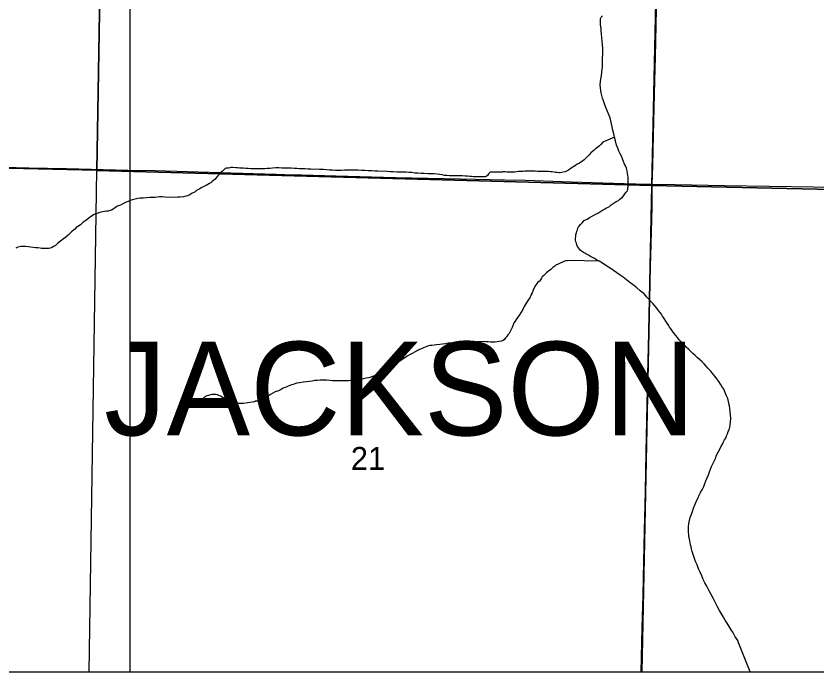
# Model space of a CAD drawing. Extents: x 0 to 68, y 0 to 52.9.
# Drawn here: x 45.735 to 47.275, y 31.143 to 32.405 of the extents above; entities that cross this region are included whole.
import ezdxf

# ---------------------------------------------------------------- set-up
doc = ezdxf.new("R2010")
doc.units = 0
for name, color, linetype in [('Default', 7, 'Continuous'), ('GM_X_County_Road', 7, 'Continuous'), ('GM_X_Minor_River', 7, 'Continuous'), ('GM_X_Township_Road', 7, 'Continuous'), ('GM_X_Township_Text', 7, 'Continuous')]:
    doc.layers.add(name, color=color, linetype=linetype)

msp = doc.modelspace()

# ---------------------------------------------------------------- linework, layer by layer
at = {"layer": 'Default'}
for p, q in [((45.9541, 31.1431), (45.9541, 38.5351)), ((42.2581, 31.1431), (49.6501, 31.1431))]:
    msp.add_line(p, q, dxfattribs=at)
for points in [[(44.8302, 33.199), (45.9077, 33.1703), (45.8901, 32.1083), (44.8166, 32.1321)], [(45.9077, 33.1703), (46.9804, 33.1394), (46.9572, 32.0794), (45.8901, 32.1083)], [(46.9804, 33.1394), (48.0507, 33.11), (48.0259, 32.0553), (46.9572, 32.0794)]]:
    msp.add_lwpolyline(points, close=True, dxfattribs=at)
for points in [[(45.8752, 31.1431), (45.8901, 32.1083), (46.9572, 32.0794), (46.938, 31.1431)], [(46.938, 31.1431), (46.9572, 32.0794), (48.0259, 32.0553), (48.0041, 31.1431)]]:
    msp.add_lwpolyline(points, dxfattribs=at)
at = {"layer": 'GM_X_County_Road'}
for points in [[(46.958, 32.0816), (46.9592, 32.1169), (46.9606, 32.176), (46.9631, 32.2809), (46.9641, 32.3268), (46.9664, 32.4187), (46.967, 32.4515), (46.9692, 32.5466), (46.9702, 32.6103)], [(46.9365, 31.1431), (46.9389, 31.2279), (46.9404, 31.2902), (46.9417, 31.3558), (46.9433, 31.4149), (46.9452, 31.4903), (46.9463, 31.5658), (46.9491, 31.6872), (46.9514, 31.7954), (46.9533, 31.861), (46.9538, 31.8906), (46.9551, 31.943), (46.9578, 32.0382), (46.958, 32.0816)]]:
    msp.add_lwpolyline(points, dxfattribs=at)
at = {"layer": 'GM_X_Minor_River'}
for points in [[(46.8624, 32.3139), (46.8624, 32.3191), (46.8624, 32.3248), (46.8628, 32.3308), (46.8628, 32.3376), (46.8628, 32.344), (46.8624, 32.35), (46.8621, 32.3569), (46.8613, 32.3633), (46.8605, 32.3709), (46.8601, 32.3765), (46.8597, 32.381), (46.8593, 32.3846), (46.8589, 32.3882), (46.8589, 32.3914), (46.8585, 32.3938), (46.8585, 32.3958), (46.8585, 32.3982), (46.8589, 32.4006), (46.8602, 32.403), (46.8626, 32.4054)], [(46.8562, 31.9335), (46.851, 31.9363), (46.847, 31.9388), (46.8442, 31.94), (46.8418, 31.9412), (46.8394, 31.9424), (46.8374, 31.9436), (46.8354, 31.9448), (46.833, 31.9464), (46.8306, 31.9476), (46.8286, 31.9492), (46.8258, 31.9501), (46.8238, 31.9513), (46.8218, 31.9529), (46.8198, 31.9545), (46.8182, 31.9569), (46.8162, 31.9593), (46.8146, 31.9617), (46.8134, 31.965), (46.8122, 31.9682), (46.811, 31.9706), (46.8106, 31.9734), (46.8106, 31.9774), (46.811, 31.981), (46.8114, 31.9846), (46.8122, 31.9882), (46.813, 31.9914), (46.8142, 31.9938), (46.815, 31.9962), (46.8159, 31.9987), (46.8175, 32.0011), (46.8199, 32.0043), (46.8231, 32.0071), (46.8271, 32.0115), (46.8332, 32.0146), (46.8376, 32.0174), (46.8496, 32.0242), (46.8545, 32.0266), (46.8585, 32.029), (46.8625, 32.0314), (46.8661, 32.0338), (46.8689, 32.0354), (46.8721, 32.037), (46.8762, 32.039), (46.879, 32.0418), (46.883, 32.0446), (46.8866, 32.047), (46.8898, 32.049), (46.893, 32.0506), (46.8959, 32.0526), (46.8983, 32.055), (46.9011, 32.057), (46.9035, 32.0598), (46.9055, 32.063), (46.9079, 32.0666), (46.9103, 32.069), (46.9112, 32.0714), (46.9112, 32.0738), (46.9116, 32.0774), (46.912, 32.0822), (46.912, 32.0862), (46.9116, 32.0902), (46.9116, 32.0943), (46.9112, 32.0983), (46.9108, 32.1023), (46.9096, 32.1075), (46.9084, 32.1127), (46.9068, 32.1167), (46.9048, 32.1204), (46.9029, 32.1252), (46.9009, 32.1304), (46.8989, 32.1356), (46.8965, 32.1401), (46.8937, 32.1453), (46.8917, 32.1509), (46.8893, 32.1569), (46.8877, 32.1654), (46.8853, 32.1722), (46.8841, 32.1786), (46.8825, 32.1858), (46.8813, 32.1919), (46.8797, 32.1979), (46.8782, 32.2035), (46.877, 32.2091), (46.875, 32.2136), (46.869, 32.2292), (46.8662, 32.2365), (46.8642, 32.2421), (46.8626, 32.2473), (46.861, 32.2521), (46.8598, 32.2574), (46.8594, 32.2622), (46.8586, 32.2674), (46.8582, 32.273), (46.8587, 32.2786), (46.8595, 32.2842), (46.8603, 32.2899), (46.8611, 32.2971), (46.8619, 32.3027), (46.8623, 32.3083), (46.8624, 32.3139)], [(46.8853, 32.1722), (46.8632, 32.1626), (46.8592, 32.1582), (46.8568, 32.1558), (46.8544, 32.1538), (46.8515, 32.1514), (46.8491, 32.1494), (46.8463, 32.147), (46.8431, 32.1446), (46.8403, 32.1418), (46.8367, 32.1382), (46.8334, 32.135), (46.8302, 32.1318), (46.827, 32.1286), (46.8238, 32.1262), (46.8206, 32.1242), (46.8178, 32.1218), (46.8137, 32.1199), (46.8105, 32.1179), (46.8025, 32.1123), (46.7993, 32.1099), (46.7973, 32.1087), (46.7932, 32.1067), (46.7904, 32.1055), (46.7868, 32.1047), (46.784, 32.1039), (46.7812, 32.1035), (46.7788, 32.1035), (46.7752, 32.1039), (46.772, 32.1043), (46.7692, 32.1047), (46.7659, 32.1052), (46.7623, 32.1056), (46.7587, 32.106), (46.7547, 32.106), (46.7499, 32.106), (46.7455, 32.106), (46.7411, 32.106), (46.7374, 32.1061), (46.733, 32.1065), (46.7294, 32.1065), (46.7258, 32.1069), (46.7218, 32.1069), (46.7178, 32.1065), (46.7134, 32.1065), (46.709, 32.1061), (46.7037, 32.1062), (46.7005, 32.1058), (46.6969, 32.1054), (46.6937, 32.105), (46.6905, 32.105), (46.6873, 32.105), (46.6837, 32.105), (46.6805, 32.105), (46.6776, 32.105), (46.6744, 32.1055), (46.6716, 32.1055), (46.6692, 32.1051), (46.6664, 32.1051), (46.6644, 32.1051), (46.6624, 32.1051), (46.66, 32.1051), (46.6576, 32.1051), (46.6556, 32.1051), (46.6536, 32.1051), (46.6516, 32.1051), (46.6463, 32.1047), (46.6435, 32.1019), (46.6411, 32.0983), (46.6387, 32.0963), (46.6367, 32.0959), (46.6327, 32.0956), (46.6287, 32.0956), (46.6254, 32.0956), (46.6218, 32.0956), (46.6182, 32.096), (46.6142, 32.096), (46.6106, 32.0964), (46.607, 32.0964), (46.603, 32.0969), (46.5982, 32.0973), (46.5933, 32.0977), (46.5885, 32.0977), (46.5825, 32.0977), (46.5773, 32.0977), (46.5729, 32.0978), (46.5681, 32.0978), (46.5632, 32.0982), (46.5588, 32.0986), (46.554, 32.0994), (46.5496, 32.1002), (46.5444, 32.1011), (46.5388, 32.1015), (46.5327, 32.1015), (46.5271, 32.1019), (46.5191, 32.1023), (46.5135, 32.1024)], [(46.5135, 32.1024), (46.5075, 32.1028), (46.5014, 32.1032), (46.4958, 32.104), (46.4902, 32.104), (46.485, 32.1045), (46.4806, 32.1045), (46.4762, 32.1045), (46.4713, 32.1049), (46.4669, 32.1049), (46.4601, 32.1053), (46.4545, 32.1054), (46.4489, 32.1058), (46.4304, 32.1066), (46.4248, 32.1067), (46.4188, 32.1071), (46.412, 32.1075), (46.4055, 32.1079), (46.3991, 32.1079), (46.3927, 32.1084), (46.3843, 32.1084), (46.3778, 32.1084), (46.3722, 32.1084), (46.3662, 32.1084), (46.3602, 32.1081), (46.3546, 32.1081), (46.3489, 32.1081), (46.3433, 32.1085), (46.3377, 32.1089), (46.3317, 32.1094), (46.3257, 32.1098), (46.3184, 32.1102), (46.3128, 32.1106), (46.3072, 32.1102), (46.3016, 32.1103), (46.296, 32.1107), (46.2899, 32.1111), (46.2847, 32.1111), (46.2799, 32.1115), (46.2747, 32.1119), (46.2695, 32.112), (46.2639, 32.1124), (46.2582, 32.1128), (46.2514, 32.1128), (46.2458, 32.1128), (46.2398, 32.1129), (46.2342, 32.1129), (46.2281, 32.1125), (46.2229, 32.1121), (46.2177, 32.1121), (46.2129, 32.1113), (46.2081, 32.111), (46.2029, 32.111), (46.198, 32.111), (46.1912, 32.1114), (46.1864, 32.1114), (46.1812, 32.1118), (46.1764, 32.1119), (46.1716, 32.1123), (46.1675, 32.1123), (46.1643, 32.1127), (46.1607, 32.1131), (46.1575, 32.1131), (46.1515, 32.1139), (46.1479, 32.1136), (46.1455, 32.1132), (46.1431, 32.1128), (46.141, 32.1128), (46.139, 32.1124), (46.1366, 32.112), (46.1346, 32.11), (46.133, 32.108), (46.131, 32.106), (46.1286, 32.104), (46.1262, 32.1016), (46.1242, 32.0992), (46.1217, 32.0968), (46.1185, 32.0932), (46.1173, 32.0912), (46.1149, 32.0896), (46.1113, 32.086), (46.1089, 32.0844), (46.1065, 32.0828), (46.1036, 32.0812), (46.1004, 32.0792), (46.0968, 32.0776), (46.0932, 32.076), (46.0904, 32.0744), (46.088, 32.0728), (46.0852, 32.0716), (46.0832, 32.07), (46.0811, 32.0688), (46.0791, 32.0672), (46.0763, 32.066), (46.0735, 32.0644), (46.0707, 32.0624), (46.0687, 32.0612), (46.0667, 32.0604), (46.0643, 32.0592), (46.0611, 32.0585), (46.0566, 32.0573)], [(46.0566, 32.0573), (46.0502, 32.0569), (46.0454, 32.0565), (46.0402, 32.0561), (46.0213, 32.0566), (46.0157, 32.0574), (46.0105, 32.0574), (46.0057, 32.0566), (46.002, 32.0562), (45.998, 32.0558), (45.9916, 32.0559), (45.9856, 32.0555), (45.9796, 32.0551), (45.9735, 32.0547), (45.9687, 32.0539), (45.9635, 32.0527), (45.9587, 32.0516), (45.9543, 32.05), (45.9503, 32.0484), (45.9462, 32.0468), (45.941, 32.0444), (45.9354, 32.0416), (45.9298, 32.0396), (45.9265, 32.0376), (45.9233, 32.0348), (45.9213, 32.0336), (45.9181, 32.0316), (45.9149, 32.0308), (45.9117, 32.03), (45.9085, 32.0296), (45.9049, 32.0289), (45.9008, 32.0285), (45.8956, 32.0273), (45.892, 32.0261), (45.8892, 32.0249), (45.886, 32.0237), (45.8836, 32.0225), (45.8812, 32.0209), (45.8779, 32.0189), (45.8747, 32.0165), (45.8711, 32.0137), (45.8671, 32.0105), (45.8631, 32.0077), (45.8586, 32.0037), (45.8534, 32.0005), (45.8502, 31.9981), (45.8474, 31.9953), (45.8446, 31.9925), (45.8413, 31.9897), (45.8381, 31.9865), (45.8345, 31.9833), (45.8301, 31.9797), (45.8261, 31.9765), (45.8144, 31.9673), (45.812, 31.9649), (45.8096, 31.9633), (45.8076, 31.9626), (45.8044, 31.9602), (45.8023, 31.9594), (45.7999, 31.9586), (45.7975, 31.9582), (45.7951, 31.9582), (45.7919, 31.9578), (45.7891, 31.9578), (45.7859, 31.9578), (45.7835, 31.9582), (45.7807, 31.9586), (45.7763, 31.959), (45.7718, 31.9595), (45.7674, 31.9599), (45.763, 31.9603), (45.7578, 31.9611), (45.753, 31.9615), (45.7482, 31.9615), (45.7438, 31.9616), (45.7381, 31.9604), (45.7341, 31.9588)], [(46.8562, 31.9335), (46.7989, 31.9349), (46.7948, 31.9345), (46.7916, 31.9341), (46.7884, 31.9329), (46.7784, 31.9285), (46.776, 31.9273), (46.7735, 31.9266), (46.7707, 31.9242), (46.7671, 31.9214), (46.7631, 31.9178), (46.7587, 31.9142), (46.7546, 31.911), (46.7518, 31.9082), (46.7494, 31.9062), (46.7466, 31.9034), (46.7454, 31.901), (46.7434, 31.8978), (46.741, 31.8954), (46.7381, 31.893), (46.7361, 31.8906), (46.7337, 31.8866), (46.7313, 31.8825), (46.7293, 31.8777), (46.7269, 31.8729), (46.7252, 31.8697), (46.7244, 31.8673), (46.7232, 31.8645), (46.722, 31.8621), (46.7204, 31.8601), (46.7184, 31.8565), (46.7156, 31.8529), (46.7136, 31.8497), (46.7119, 31.8461), (46.7095, 31.8405), (46.7063, 31.8353), (46.7027, 31.8305), (46.6995, 31.8257), (46.6966, 31.8213), (46.6942, 31.8181), (46.6922, 31.8149), (46.6906, 31.8112), (46.6886, 31.806), (46.687, 31.802), (46.6849, 31.7984), (46.6829, 31.7944), (46.6805, 31.7916), (46.6785, 31.7888), (46.6761, 31.786), (46.6741, 31.7828), (46.6717, 31.7808), (46.6684, 31.7796), (46.6556, 31.7776), (46.6516, 31.7777), (46.6472, 31.7777), (46.6427, 31.7781), (46.6383, 31.7785), (46.6335, 31.7789), (46.6283, 31.7785), (46.6223, 31.7782), (46.6159, 31.7778), (46.6074, 31.7778), (46.6022, 31.7778), (46.597, 31.7778), (46.5918, 31.7779), (46.5866, 31.7775), (46.5817, 31.7771), (46.5769, 31.7767), (46.5713, 31.7759), (46.5657, 31.7755), (46.5601, 31.7747), (46.5548, 31.774), (46.5496, 31.7732), (46.5432, 31.7724), (46.5384, 31.772), (46.534, 31.7716), (46.5304, 31.7712), (46.5275, 31.7704), (46.5247, 31.7696), (46.5215, 31.7684), (46.5179, 31.7669), (46.5143, 31.7649), (46.5103, 31.7633), (46.5066, 31.7617), (46.501, 31.7585), (46.4962, 31.7557), (46.491, 31.7533), (46.4866, 31.7505), (46.4821, 31.7477), (46.4773, 31.7445), (46.4725, 31.7413), (46.4685, 31.7377), (46.4644, 31.7345), (46.46, 31.7321), (46.456, 31.7297), (46.4524, 31.7265), (46.448, 31.7249), (46.4447, 31.7229), (46.4419, 31.7209), (46.4383, 31.719), (46.4339, 31.717)], [(47.0296, 31.4345), (47.0312, 31.4406), (47.0333, 31.4466), (47.0353, 31.4522), (47.0377, 31.4586), (47.0405, 31.4658), (47.043, 31.4722), (47.0462, 31.4782), (47.0486, 31.4834), (47.051, 31.4882), (47.0539, 31.4935), (47.0571, 31.5003), (47.0591, 31.5055), (47.0611, 31.5111), (47.0635, 31.5167), (47.0664, 31.5223), (47.0684, 31.5279), (47.0704, 31.5331), (47.0724, 31.5383), (47.0748, 31.5435), (47.0773, 31.5488), (47.0797, 31.5536), (47.0817, 31.5604), (47.0849, 31.566), (47.0878, 31.5716), (47.0902, 31.5764), (47.093, 31.5816), (47.0954, 31.586), (47.0974, 31.59), (47.0994, 31.5932), (47.1011, 31.5976), (47.1027, 31.6016), (47.1043, 31.6057), (47.1059, 31.6093), (47.1075, 31.6141), (47.1083, 31.6177), (47.1092, 31.6313), (47.1088, 31.6373), (47.108, 31.6442), (47.1072, 31.6498), (47.1064, 31.655), (47.1056, 31.6598), (47.1048, 31.6638), (47.1036, 31.6695), (47.1012, 31.6743), (47.0993, 31.6791), (47.0973, 31.6839), (47.0949, 31.6883), (47.0921, 31.6924), (47.0893, 31.6972), (47.0861, 31.702), (47.0821, 31.7069), (47.0789, 31.7117), (47.0745, 31.7165), (47.0705, 31.7217), (47.0653, 31.7274), (47.0617, 31.7318), (47.0577, 31.7362), (47.0532, 31.7403), (47.0488, 31.7443), (47.0448, 31.7479), (47.0404, 31.7519), (47.0364, 31.756), (47.0324, 31.76), (47.028, 31.7644), (47.0236, 31.768), (47.0196, 31.7733), (47.0136, 31.7781), (47.01, 31.7821), (47.0064, 31.7866), (47.0032, 31.7906), (47, 31.7946), (46.9972, 31.799), (46.9944, 31.803), (46.9916, 31.8067), (46.9892, 31.8107), (46.9868, 31.8143), (46.9844, 31.8183), (46.9808, 31.8232), (46.978, 31.8276), (46.9756, 31.8316), (46.9728, 31.8352), (46.9696, 31.8392), (46.9668, 31.8429), (46.9636, 31.8469), (46.96, 31.8513), (46.9476, 31.8646), (46.9424, 31.871), (46.9348, 31.8767), (46.9288, 31.8823), (46.922, 31.8872), (46.9151, 31.8928), (46.9087, 31.8976), (46.9023, 31.9025), (46.8963, 31.9069), (46.8899, 31.9113), (46.8835, 31.9154), (46.8771, 31.9198), (46.8711, 31.9238), (46.8627, 31.9295), (46.8562, 31.9335)], [(46.4339, 31.717), (46.4291, 31.7146), (46.413, 31.7094), (46.4078, 31.7082), (46.403, 31.7074), (46.3969, 31.7062), (46.3917, 31.7051), (46.3861, 31.7043), (46.3805, 31.7039), (46.3749, 31.7035), (46.3696, 31.7035), (46.3644, 31.7035), (46.3596, 31.7036), (46.3556, 31.7036), (46.3524, 31.7036), (46.3492, 31.7036), (46.3468, 31.7036), (46.3432, 31.7036), (46.3379, 31.704), (46.3315, 31.7044), (46.3251, 31.7045), (46.3195, 31.7045), (46.3139, 31.7041), (46.309, 31.7037), (46.3042, 31.7029), (46.299, 31.7021), (46.293, 31.7014), (46.287, 31.7006), (46.2797, 31.6994), (46.2749, 31.6986), (46.2709, 31.6974), (46.2677, 31.6962), (46.2645, 31.6954), (46.2613, 31.6942), (46.258, 31.693), (46.2552, 31.6918), (46.252, 31.6907), (46.2484, 31.6891), (46.2444, 31.6867), (46.2396, 31.6839), (46.2331, 31.6819), (46.2283, 31.6795), (46.2239, 31.6771), (46.2199, 31.6743), (46.2155, 31.6723), (46.2114, 31.6699), (46.2074, 31.6679), (46.203, 31.6659), (46.199, 31.6643), (46.1954, 31.6639), (46.193, 31.6632), (46.1885, 31.6624), (46.1721, 31.66), (46.1669, 31.66), (46.162, 31.66), (46.158, 31.6601), (46.1548, 31.6609), (46.1508, 31.6617), (46.1472, 31.6629), (46.1436, 31.6645), (46.1396, 31.6673), (46.1344, 31.6698), (46.1308, 31.6722), (46.128, 31.6738), (46.1248, 31.6754), (46.1219, 31.6762), (46.1187, 31.677), (46.1151, 31.677), (46.1119, 31.6771), (46.1083, 31.6763), (46.1047, 31.6751), (46.1015, 31.6743), (46.0979, 31.6723), (46.0958, 31.6703), (46.0938, 31.6675), (46.0918, 31.6651), (46.0902, 31.6627), (46.089, 31.6603), (46.0874, 31.6575), (46.0858, 31.6555)], [(47.1463, 31.1431), (47.1258, 31.1947), (47.1242, 31.1991), (47.1226, 31.2035), (47.1202, 31.2075), (47.1178, 31.2107), (47.1158, 31.2148), (47.113, 31.2196), (47.1102, 31.224), (47.1058, 31.2308), (47.1022, 31.2369), (47.0986, 31.2425), (47.095, 31.2485), (47.091, 31.255), (47.0874, 31.2614), (47.0838, 31.2686), (47.0798, 31.2759), (47.0758, 31.2839), (47.0714, 31.2919), (47.0674, 31.2992), (47.0634, 31.308), (47.0594, 31.3149), (47.0562, 31.3213), (47.0534, 31.3281), (47.0503, 31.3349), (47.0471, 31.3418), (47.0443, 31.349), (47.0415, 31.3554), (47.0359, 31.3711), (47.0347, 31.3751), (47.0335, 31.3799), (47.0327, 31.384), (47.0319, 31.3876), (47.0311, 31.3916), (47.0303, 31.3956), (47.0295, 31.3996), (47.0288, 31.4036), (47.0284, 31.4077), (47.028, 31.4117), (47.0276, 31.4169), (47.0276, 31.4221), (47.0284, 31.4289), (47.0296, 31.4345)]]:
    msp.add_lwpolyline(points, dxfattribs=at)
at = {"layer": 'GM_X_Township_Road'}
for points in [[(45.3537, 32.1212), (45.4639, 32.1189), (45.5033, 32.1183), (45.5853, 32.1167), (45.6607, 32.1155), (45.7592, 32.1133), (45.8313, 32.1119), (45.9494, 32.1088), (46.0019, 32.108), (46.1266, 32.1042), (46.2348, 32.101), (46.2676, 32.1), (46.284, 32.0999), (46.3496, 32.0978), (46.4644, 32.0947), (46.5891, 32.0917), (46.6743, 32.0902), (46.7137, 32.0894), (46.8023, 32.0865), (46.904, 32.0833), (46.9498, 32.0816), (46.958, 32.0816)], [(46.958, 32.0816), (47.0023, 32.0811), (47.0975, 32.0792), (47.2681, 32.0765), (47.3206, 32.0756), (47.3665, 32.0749), (47.4191, 32.0739), (47.4679, 32.0731), (47.4939, 32.0723), (47.5266, 32.0715), (47.5626, 32.0704), (47.6118, 32.069), (47.7003, 32.0661), (47.7364, 32.0652), (47.9201, 32.0596), (47.9955, 32.057), (48.0184, 32.0568), (48.0241, 32.0567)]]:
    msp.add_lwpolyline(points, dxfattribs=at)

# ---------------------------------------------------------------- texts
at = {"layer": 'Default'}
msp.add_text('21', height=0.0442, rotation=0, dxfattribs=at).set_placement((46.3785, 31.5319))
at = {"layer": 'GM_X_Township_Text'}
msp.add_text('JACKSON', height=0.18, rotation=0, dxfattribs=at).set_placement((45.9039, 31.5984))

doc.saveas('drawing.dxf')
